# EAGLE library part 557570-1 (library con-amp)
AMP connector
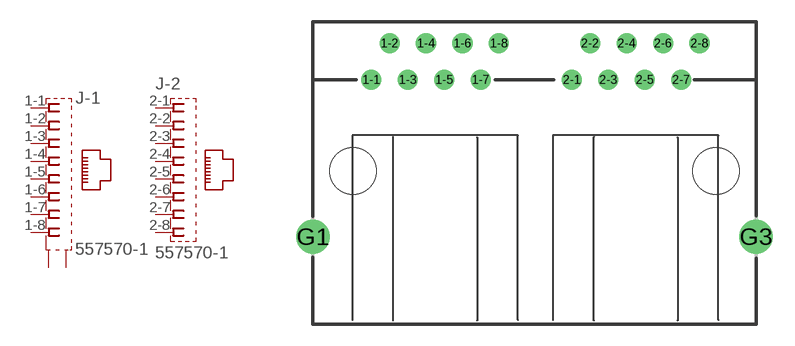
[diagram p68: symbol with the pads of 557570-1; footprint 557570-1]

Designator prefix J; gates -1=JACK8SH -2=JACK8_SH

## 557570-1 (MPN: 5557570-1; OC_FARNELL: unknown; OC_NEWARK: 19R2788)  [557570-1]
1-1  -1:1  pas
1-2  -1:2  pas
1-3  -1:3  pas
1-4  -1:4  pas
1-5  -1:5  pas
1-6  -1:6  pas
1-7  -1:7  pas
1-8  -1:8  pas
2-1  -2:1  pas
2-2  -2:2  pas
2-3  -2:3  pas
2-4  -2:4  pas
2-5  -2:5  pas
2-6  -2:6  pas
2-7  -2:7  pas
2-8  -2:8  pas
G1  -1:S2  pas
G3  -1:S1  pas

## Footprint 557570-1 (pad centres in mm)
Modular Jack Shielded
drill 0.889 round: 1-1 -11.43,6.35; 1-2 -10.16,8.89; 1-3 -8.89,6.35; 1-4 -7.62,8.89; 1-5 -6.35,6.35; 1-6 -5.08,8.89; 1-7 -3.81,6.35; 1-8 -2.54,8.89; 2-1 2.54,6.35; 2-2 3.81,8.89; 2-3 5.08,6.35; 2-4 6.35,8.89; 2-5 7.62,6.35; 2-6 8.89,8.89; 2-7 10.16,6.35; 2-8 11.43,8.89
drill 1.575 pad 2.184 round: G1 -15.494,-4.572; G3 15.367,-4.572
hole 3.251 at -12.7,0
hole 3.251 at 12.573,0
